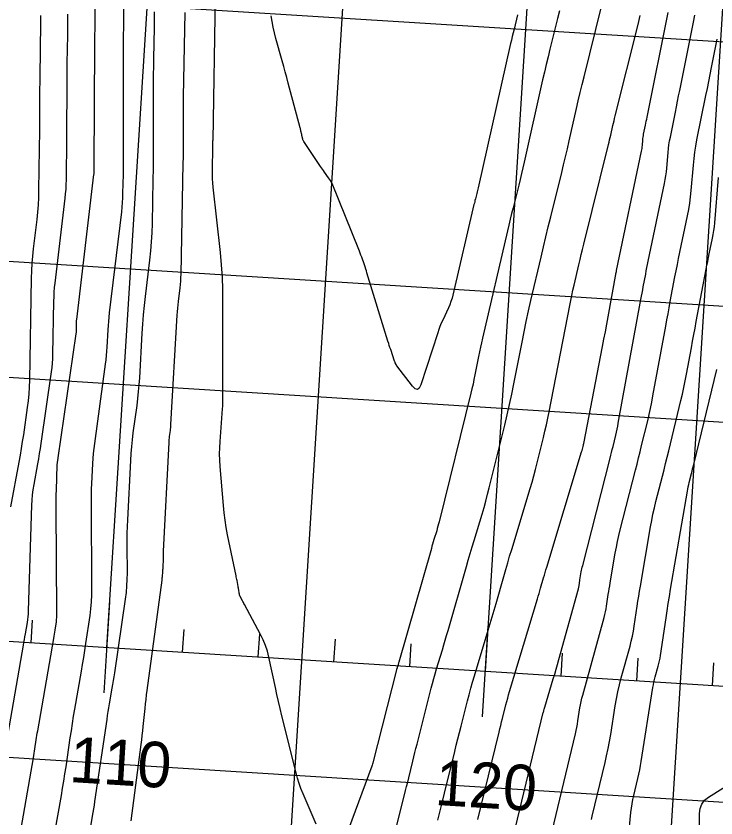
# Model space of a CAD drawing. Extents: x 658976 to 668721, y 639543 to 647196.
# Drawn here: x 661687.6 to 661779.9, y 641890.7 to 641996.4 of the extents above; entities that cross this region are included whole.
import ezdxf

# ---------------------------------------------------------------- set-up
doc = ezdxf.new("R2010")
doc.units = 0
for name, color, linetype in [('Ex_Major Contours', 7, 'Continuous'), ('Ex_Minor Contours', 7, 'Continuous'), ('R_Axis', 7, 'Continuous'), ('R_Axis Annot', 7, 'Continuous'), ('R_Grid', 7, 'Continuous')]:
    doc.layers.add(name, color=color, linetype=linetype)

msp = doc.modelspace()

# ---------------------------------------------------------------- linework, layer by layer
at = {"layer": 'Ex_Major Contours'}
for points in [[(661687.83, 641886.53), (661689.93, 641898.61), (661689.98, 641898.9), (661690.03, 641899.2), (661690.08, 641899.49), (661690.12, 641899.79), (661690.29, 641900.97), (661690.34, 641901.26), (661690.38, 641901.55), (661690.43, 641901.85), (661690.48, 641902.14), (661692.61, 641914.34), (661692.65, 641914.62), (661692.7, 641914.89), (661692.74, 641915.17), (661692.78, 641915.44), (661692.95, 641916.54), (661692.98, 641916.82), (661693.01, 641917.1), (661693.02, 641917.37), (661693.02, 641917.65), (661692.93, 641931.59), (661692.93, 641932.17), (661692.93, 641932.74), (661692.94, 641933.32), (661692.95, 641933.9), (661693.06, 641937.19), (661693.06, 641937.27), (661693.07, 641937.35), (661693.08, 641937.43), (661693.09, 641937.51), (661693.15, 641937.83), (661693.16, 641937.91), (661693.18, 641937.99), (661693.19, 641938.07), (661693.2, 641938.15), (661695.55, 641954.48), (661695.57, 641954.57), (661695.58, 641954.66), (661695.58, 641954.75), (661695.58, 641954.85), (661695.6, 641955.98), (661695.61, 641956.08), (661695.61, 641956.18), (661695.62, 641956.27), (661695.63, 641956.37), (661697.9, 641975.47), (661697.91, 641975.56), (661697.92, 641975.66), (661697.92, 641975.75), (661697.92, 641975.84), (661697.93, 641976.21), (661697.93, 641976.31), (661697.93, 641976.4), (661697.93, 641976.49), (661697.93, 641976.58), (661698.02, 641992.66), (661698.02, 641992.92), (661698.02, 641993.19), (661698.02, 641993.45), (661698.03, 641993.72), (661698.04, 641994.78), (661698.04, 641995.05), (661698.05, 641995.32), (661698.05, 641995.58), (661698.05, 641995.85), (661697.98, 642004.95)], [(661753.76, 641996.52), (661753.29, 641994.63), (661753.17, 641994.16), (661753.05, 641993.69), (661752.94, 641993.21), (661752.83, 641992.74), (661748.54, 641973.74), (661748.5, 641973.55), (661748.46, 641973.37), (661748.42, 641973.19), (661748.37, 641973), (661748.19, 641972.27), (661748.14, 641972.08), (661748.1, 641971.9), (661748.06, 641971.72), (661748.01, 641971.53), (661745.22, 641959.6), (661745.11, 641959.17), (661744.97, 641958.74), (661744.82, 641958.33), (661744.64, 641957.92), (661743.88, 641956.29), (661743.69, 641955.88), (661743.52, 641955.46), (661743.37, 641955.05), (661743.22, 641954.62), (661740.99, 641947.76), (661740.78, 641947.33), (661740.54, 641947.15), (661740.25, 641947.24), (661739.91, 641947.57), (661737.84, 641950.27), (661737.81, 641950.31), (661737.78, 641950.36), (661737.75, 641950.41), (661737.73, 641950.46), (661737.63, 641950.67), (661737.61, 641950.72), (661737.59, 641950.78), (661737.57, 641950.83), (661737.55, 641950.88), (661737.03, 641952.41), (661736.93, 641952.68), (661736.84, 641952.96), (661736.76, 641953.23), (661736.67, 641953.51), (661733.9, 641962.51), (661733.82, 641962.77), (661733.73, 641963.03), (661733.65, 641963.3), (661733.56, 641963.56), (661733.2, 641964.6), (661733.11, 641964.86), (661733.02, 641965.11), (661732.92, 641965.37), (661732.82, 641965.62), (661729.29, 641974.28), (661729.2, 641974.49), (661729.09, 641974.69), (661728.97, 641974.89), (661728.84, 641975.07), (661728.29, 641975.81), (661728.16, 641976), (661728.03, 641976.19), (661727.89, 641976.37), (661727.77, 641976.56), (661725.56, 641979.85), (661725.52, 641979.92), (661725.49, 641979.99), (661725.46, 641980.06), (661725.44, 641980.14), (661725.37, 641980.44), (661725.35, 641980.52), (661725.33, 641980.6), (661725.32, 641980.67), (661725.3, 641980.75), (661725.19, 641981.22), (661725.17, 641981.33), (661725.15, 641981.43), (661725.12, 641981.53), (661725.09, 641981.64), (661723.53, 641987.53), (661723.33, 641988.26), (661723.13, 641989), (661722.93, 641989.74), (661722.72, 641990.47), (661721.9, 641993.41), (661721.7, 641994.15), (661721.53, 641994.89), (661721.39, 641995.64), (661721.26, 641996.39)], [(661752.9, 641887.04), (661757.15, 641904.55), (661757.17, 641904.62), (661757.18, 641904.68), (661757.2, 641904.74), (661757.21, 641904.8), (661757.28, 641905.05), (661757.29, 641905.11), (661757.31, 641905.17), (661757.33, 641905.23), (661757.35, 641905.29), (661758.46, 641909), (661758.65, 641909.64), (661758.84, 641910.28), (661759.02, 641910.92), (661759.2, 641911.56), (661761.78, 641920.87), (661761.8, 641920.97), (661761.82, 641921.07), (661761.84, 641921.17), (661761.86, 641921.27), (661761.92, 641921.68), (661761.94, 641921.78), (661761.95, 641921.88), (661761.97, 641921.98), (661761.98, 641922.08), (661762.16, 641923.12), (661762.2, 641923.32), (661762.24, 641923.53), (661762.29, 641923.73), (661762.34, 641923.93), (661765.96, 641938.1), (661766.05, 641938.48), (661766.15, 641938.86), (661766.24, 641939.24), (661766.34, 641939.62), (661766.71, 641941.15), (661766.8, 641941.53), (661766.88, 641941.92), (661766.96, 641942.3), (661767.04, 641942.69), (661770.02, 641959.02), (661770.1, 641959.44), (661770.18, 641959.86), (661770.25, 641960.28), (661770.33, 641960.7), (661770.65, 641962.37), (661770.73, 641962.79), (661770.81, 641963.21), (661770.9, 641963.63), (661770.98, 641964.05), (661773.13, 641974.31), (661773.23, 641974.81), (661773.31, 641975.32), (661773.38, 641975.83), (661773.43, 641976.34), (661773.6, 641978.4), (661773.66, 641978.91), (661773.72, 641979.42), (661773.8, 641979.93), (661773.9, 641980.43), (661774.56, 641983.71), (661774.7, 641984.42), (661774.85, 641985.14), (661774.99, 641985.85), (661775.13, 641986.57), (661776.76, 641994.67), (661776.94, 641995.58), (661777.11, 641996.49)]]:
    msp.add_lwpolyline(points, dxfattribs=at)
at = {"layer": 'Ex_Minor Contours'}
for points in [[(661692.76, 641888.74), (661693.61, 641893.64), (661693.77, 641894.59), (661693.93, 641895.53), (661694.08, 641896.48), (661694.22, 641897.43), (661694.78, 641901.22), (661694.92, 641902.17), (661695.07, 641903.12), (661695.22, 641904.07), (661695.38, 641905.01), (661696.25, 641910.01), (661696.41, 641910.92), (661696.56, 641911.84), (661696.7, 641912.75), (661696.84, 641913.67), (661697.38, 641917.34), (661697.5, 641918.25), (661697.58, 641919.17), (661697.63, 641920.1), (661697.64, 641921.02), (661697.56, 641932.09), (661697.56, 641932.75), (661697.57, 641933.41), (661697.59, 641934.07), (661697.62, 641934.73), (661697.75, 641937.38), (661697.79, 641938.04), (661697.84, 641938.7), (661697.91, 641939.35), (661698, 641940.01), (661699.42, 641950.49), (661699.49, 641951.05), (661699.55, 641951.62), (661699.6, 641952.18), (661699.64, 641952.74), (661699.77, 641955.01), (661699.81, 641955.57), (661699.86, 641956.13), (661699.91, 641956.7), (661699.97, 641957.26), (661701.56, 641970.56), (661701.63, 641971.17), (661701.68, 641971.79), (661701.71, 641972.41), (661701.73, 641973.02), (661701.78, 641975.5), (661701.79, 641976.12), (661701.8, 641976.73), (661701.8, 641977.35), (661701.8, 641977.97), (661701.79, 641992.45), (661701.79, 641992.77), (661701.79, 641993.08), (661701.79, 641993.39), (661701.8, 641993.71), (661701.82, 641994.96), (661701.82, 641995.27), (661701.83, 641995.58), (661701.82, 641995.89), (661701.82, 641996.21), (661701.62, 642008.21)], [(661727.2, 641889.86), (661725.47, 641893.87), (661725.2, 641894.54), (661724.95, 641895.22), (661724.73, 641895.92), (661724.55, 641896.62), (661722.68, 641904.15), (661722.45, 641905.08), (661722.23, 641906), (661722.02, 641906.93), (661721.82, 641907.86), (661720.96, 641911.88), (661720.77, 641912.65), (661720.52, 641913.4), (661720.22, 641914.13), (661719.87, 641914.84), (661717.74, 641918.81), (661717.68, 641918.93), (661717.61, 641919.06), (661717.54, 641919.19), (661717.48, 641919.31), (661717.19, 641919.87), (661717.15, 641919.97), (661717.11, 641920.08), (661717.08, 641920.18), (661717.06, 641920.3), (661716.99, 641920.74), (661716.97, 641920.85), (661716.95, 641920.96), (661716.93, 641921.08), (661716.91, 641921.19), (661716.77, 641921.95), (661716.74, 641922.11), (661716.71, 641922.27), (661716.67, 641922.44), (661716.64, 641922.6), (661715.51, 641927.99), (661715.33, 641928.95), (661715.18, 641929.91), (661715.05, 641930.87), (661714.96, 641931.84), (661714.54, 641936.99), (661714.49, 641937.82), (661714.47, 641938.65), (661714.48, 641939.47), (661714.53, 641940.3), (661714.86, 641944.6), (661714.88, 641944.93), (661714.9, 641945.26), (661714.91, 641945.59), (661714.91, 641945.93), (661714.9, 641947.25), (661714.9, 641947.58), (661714.9, 641947.91), (661714.9, 641948.25), (661714.9, 641948.58), (661714.91, 641958.7), (661714.89, 641960.33), (661714.83, 641961.95), (661714.72, 641963.58), (661714.57, 641965.2), (661713.63, 641973.82), (661713.58, 641974.37), (661713.54, 641974.91), (661713.53, 641975.46), (661713.53, 641976.01), (661713.59, 641979.16), (661713.59, 641979.23), (661713.59, 641979.3), (661713.59, 641979.38), (661713.59, 641979.45), (661713.59, 641979.74), (661713.59, 641979.81), (661713.59, 641979.88), (661713.59, 641979.95), (661713.6, 641980.03), (661713.92, 641999.04)], [(661736.72, 641885.34), (661738.85, 641893.72), (661738.99, 641894.27), (661739.13, 641894.83), (661739.27, 641895.39), (661739.41, 641895.94), (661739.95, 641898.17), (661740.08, 641898.73), (661740.22, 641899.29), (661740.36, 641899.84), (661740.5, 641900.4), (661742.38, 641907.78), (661742.55, 641908.41), (661742.72, 641909.05), (661742.9, 641909.68), (661743.08, 641910.32), (661743.84, 641912.84), (661744.03, 641913.47), (661744.22, 641914.1), (661744.4, 641914.73), (661744.59, 641915.36), (661747, 641923.8), (661747.25, 641924.67), (661747.51, 641925.53), (661747.76, 641926.4), (661748.02, 641927.26), (661749.07, 641930.72), (661749.33, 641931.58), (661749.57, 641932.45), (661749.8, 641933.33), (661750.03, 641934.2), (661752.07, 641942.46), (661752.4, 641943.82), (661752.71, 641945.18), (661753, 641946.55), (661753.27, 641947.91), (661754.34, 641953.4), (661754.61, 641954.77), (661754.9, 641956.13), (661755.19, 641957.5), (661755.51, 641958.86), (661756.85, 641964.61), (661757.16, 641965.94), (661757.48, 641967.26), (661757.8, 641968.59), (661758.13, 641969.91), (661759.57, 641975.73), (661759.82, 641976.78), (661760.07, 641977.83), (661760.32, 641978.89), (661760.56, 641979.94), (661761.51, 641984.17), (661761.76, 641985.22), (661762, 641986.28), (661762.26, 641987.33), (661762.52, 641988.38), (661764.84, 641997.63)], [(661684.29, 641888.9), (661688.6, 641913.43), (661688.67, 641913.8), (661688.73, 641914.18), (661688.8, 641914.56), (661688.86, 641914.93), (661689.12, 641916.44), (661689.18, 641916.82), (661689.23, 641917.2), (661689.26, 641917.58), (661689.28, 641917.96), (661689.71, 641931.88), (661689.74, 641932.57), (661689.8, 641933.25), (661689.89, 641933.93), (661690, 641934.61), (661690.5, 641937.33), (661690.62, 641938.01), (661690.74, 641938.69), (661690.85, 641939.37), (661690.95, 641940.05), (661692.31, 641949.49), (661692.38, 641950.05), (661692.44, 641950.61), (661692.47, 641951.18), (661692.49, 641951.75), (661692.62, 641958.77), (661692.64, 641959.38), (661692.67, 641959.98), (661692.72, 641960.58), (661692.78, 641961.18), (661694.11, 641972.36), (661694.17, 641972.96), (661694.22, 641973.57), (661694.25, 641974.18), (661694.27, 641974.78), (661694.3, 641977.21), (661694.31, 641977.82), (661694.32, 641978.43), (661694.32, 641979.04), (661694.32, 641979.65), (661694.37, 641988.5), (661694.38, 641989.24), (661694.38, 641989.98), (661694.39, 641990.72), (661694.4, 641991.45), (661694.44, 641994.41), (661694.45, 641995.14), (661694.45, 641995.88), (661694.45, 641996.62)], [(661690.87, 641996.45), (661690.86, 641995.96), (661690.86, 641995.48), (661690.76, 641988.34), (661690.75, 641987.56), (661690.74, 641986.77), (661690.74, 641985.98), (661690.73, 641985.19), (661690.71, 641982.04), (661690.71, 641981.25), (661690.7, 641980.46), (661690.69, 641979.68), (661690.68, 641978.89), (661690.61, 641973.42), (661690.58, 641972.45), (661690.53, 641971.48), (661690.46, 641970.52), (661690.36, 641969.55), (661689.9, 641965.71), (661689.8, 641964.74), (661689.72, 641963.78), (661689.66, 641962.81), (661689.64, 641961.84), (661689.39, 641948.37), (661689.36, 641947.47), (661689.31, 641946.57), (661689.22, 641945.66), (661689.1, 641944.77), (661688.59, 641941.17), (661688.45, 641940.28), (661688.31, 641939.38), (661688.16, 641938.49), (661688, 641937.59), (661686.9, 641931.68)], [(661705.85, 641996.92), (661705.84, 641995.89), (661705.83, 641994.86), (661705.76, 641990.74), (661705.74, 641989.71), (661705.73, 641988.68), (661705.73, 641987.65), (661705.73, 641986.62), (661705.73, 641980.34), (661705.73, 641978.96), (661705.72, 641977.59), (661705.7, 641976.22), (661705.68, 641974.85), (661705.57, 641969.03), (661705.53, 641967.82), (661705.46, 641966.62), (661705.36, 641965.41), (661705.23, 641964.21), (661704.66, 641959.4), (661704.52, 641958.2), (661704.41, 641956.99), (661704.31, 641955.78), (661704.23, 641954.58), (661703.89, 641948.69), (661703.83, 641947.78), (661703.75, 641946.87), (661703.65, 641945.96), (661703.54, 641945.05), (661703.04, 641941.43), (661702.93, 641940.53), (661702.84, 641939.62), (661702.76, 641938.71), (661702.71, 641937.79), (661702.32, 641929.97), (661702.28, 641929.1), (661702.25, 641928.22), (661702.24, 641927.35), (661702.24, 641926.48), (661702.27, 641922.99), (661702.25, 641922.12), (661702.21, 641921.25), (661702.13, 641920.38), (661702.02, 641919.52), (661700.59, 641909.8), (661700.52, 641909.29), (661700.43, 641908.78), (661700.35, 641908.27), (661700.26, 641907.76), (661699.91, 641905.71), (661699.82, 641905.2), (661699.74, 641904.69), (661699.66, 641904.18), (661699.58, 641903.67), (661697.99, 641892.82), (661697.92, 641892.34), (661697.84, 641891.87), (661697.76, 641891.39), (661697.68, 641890.92), (661697.35, 641889.02)], [(661709.87, 641996.82), (661709.68, 641985.74), (661709.67, 641985.01), (661709.66, 641984.28), (661709.66, 641983.55), (661709.66, 641982.82), (661709.66, 641979.91), (661709.66, 641979.18), (661709.66, 641978.45), (661709.65, 641977.72), (661709.64, 641976.99), (661709.35, 641962.34), (661709.33, 641961.89), (661709.31, 641961.44), (661709.27, 641960.99), (661709.22, 641960.54), (661709.01, 641958.75), (661708.96, 641958.3), (661708.92, 641957.85), (661708.88, 641957.4), (661708.85, 641956.95), (661708.01, 641942.52), (661708, 641942.32), (661707.98, 641942.12), (661707.96, 641941.92), (661707.94, 641941.73), (661707.83, 641940.94), (661707.81, 641940.74), (661707.79, 641940.54), (661707.77, 641940.34), (661707.76, 641940.15), (661707.04, 641925.85), (661707.03, 641925.6), (661707.02, 641925.35), (661707.01, 641925.1), (661707.01, 641924.85), (661706.97, 641923.63), (661706.97, 641923.49), (661706.96, 641923.36), (661706.95, 641923.22), (661706.94, 641923.09), (661706.89, 641922.54), (661706.88, 641922.41), (661706.86, 641922.27), (661706.85, 641922.14), (661706.83, 641922), (661704.88, 641907.48), (661704.8, 641906.89), (661704.73, 641906.3), (661704.66, 641905.7), (661704.6, 641905.11), (661704.35, 641902.73), (661704.29, 641902.14), (661704.22, 641901.54), (661704.15, 641900.95), (661704.08, 641900.36), (661702.77, 641890.3)], [(661759.29, 641997.07), (661759.04, 641996.05), (661758.03, 641992.01), (661757.78, 641990.99), (661757.53, 641989.98), (661757.29, 641988.97), (661757.06, 641987.95), (661754.61, 641977.11), (661754.44, 641976.36), (661754.27, 641975.6), (661754.09, 641974.85), (661753.9, 641974.1), (661753.16, 641971.09), (661752.97, 641970.33), (661752.79, 641969.58), (661752.61, 641968.83), (661752.43, 641968.07), (661749.12, 641953.92), (661748.98, 641953.31), (661748.85, 641952.71), (661748.72, 641952.1), (661748.6, 641951.5), (661748.13, 641949.06), (661748.01, 641948.46), (661747.88, 641947.85), (661747.74, 641947.25), (661747.6, 641946.65), (661743.41, 641929.71), (661743.33, 641929.42), (661743.26, 641929.12), (661743.17, 641928.83), (661743.09, 641928.54), (661742.73, 641927.37), (661742.64, 641927.08), (661742.56, 641926.78), (661742.47, 641926.49), (661742.39, 641926.2), (661738.09, 641911.19), (661738.06, 641911.1), (661738.04, 641911.02), (661738.01, 641910.93), (661737.99, 641910.85), (661737.89, 641910.52), (661737.86, 641910.43), (661737.84, 641910.35), (661737.81, 641910.26), (661737.79, 641910.18), (661734.68, 641897.95), (661734.67, 641897.91), (661734.66, 641897.87), (661734.65, 641897.84), (661734.64, 641897.8), (661734.59, 641897.65), (661734.58, 641897.62), (661734.57, 641897.58), (661734.56, 641897.54), (661734.54, 641897.51), (661730.59, 641886.82)], [(661743.25, 641890.38), (661743.47, 641891.26), (661743.7, 641892.15), (661743.92, 641893.03), (661744.13, 641893.92), (661745.47, 641899.41), (661745.67, 641900.25), (661745.88, 641901.08), (661746.09, 641901.92), (661746.3, 641902.75), (661747.15, 641906.09), (661747.36, 641906.92), (661747.59, 641907.76), (661747.83, 641908.58), (661748.07, 641909.41), (661749.88, 641915.41), (661750.14, 641916.3), (661750.4, 641917.18), (661750.66, 641918.07), (661750.92, 641918.96), (661751.93, 641922.51), (661752.19, 641923.4), (661752.45, 641924.28), (661752.71, 641925.17), (661752.98, 641926.05), (661755.42, 641934.12), (661755.67, 641934.95), (661755.9, 641935.78), (661756.13, 641936.62), (661756.34, 641937.46), (661757.17, 641940.82), (661757.37, 641941.66), (661757.57, 641942.5), (661757.75, 641943.35), (661757.92, 641944.2), (661760.64, 641958.21), (661760.77, 641958.89), (661760.91, 641959.56), (661761.06, 641960.24), (661761.22, 641960.91), (661761.85, 641963.6), (661762, 641964.27), (661762.16, 641964.95), (661762.33, 641965.62), (661762.49, 641966.29), (661765.74, 641979.44), (661765.82, 641979.75), (661765.89, 641980.06), (661765.97, 641980.38), (661766.04, 641980.69), (661766.32, 641981.95), (661766.39, 641982.26), (661766.47, 641982.58), (661766.54, 641982.89), (661766.62, 641983.2), (661769.66, 641995.28), (661769.75, 641995.67), (661769.84, 641996.05), (661769.92, 641996.43)], [(661748.51, 641890.48), (661751.31, 641901.98), (661751.42, 641902.43), (661751.53, 641902.88), (661751.64, 641903.33), (661751.76, 641903.78), (661752.21, 641905.57), (661752.33, 641906.02), (661752.45, 641906.46), (661752.58, 641906.91), (661752.71, 641907.35), (661756.38, 641919.57), (661756.49, 641919.92), (661756.59, 641920.26), (661756.69, 641920.61), (661756.79, 641920.95), (661757.19, 641922.34), (661757.29, 641922.69), (661757.39, 641923.03), (661757.49, 641923.38), (661757.6, 641923.72), (661762.2, 641938.93), (661762.23, 641939.01), (661762.25, 641939.1), (661762.28, 641939.19), (661762.3, 641939.28), (661762.39, 641939.64), (661762.41, 641939.73), (661762.43, 641939.82), (661762.45, 641939.91), (661762.47, 641940.01), (661764.95, 641952.81), (661765.14, 641953.79), (661765.33, 641954.76), (661765.51, 641955.74), (661765.69, 641956.72), (661766.76, 641962.55), (661766.76, 641962.58), (661766.77, 641962.6), (661766.77, 641962.63), (661766.78, 641962.65), (661766.79, 641962.75), (661766.8, 641962.78), (661766.8, 641962.8), (661766.81, 641962.83), (661766.81, 641962.85), (661770.1, 641978.56), (661770.14, 641978.74), (661770.17, 641978.93), (661770.19, 641979.12), (661770.21, 641979.3), (661770.28, 641980.05), (661770.29, 641980.24), (661770.32, 641980.43), (661770.35, 641980.61), (661770.38, 641980.8), (661770.63, 641982), (661770.68, 641982.26), (661770.73, 641982.52), (661770.78, 641982.78), (661770.84, 641983.04), (661773.6, 641996.86)], [(661758.04, 641887.84), (661761.38, 641901.77), (661761.47, 641902.19), (661761.56, 641902.61), (661761.64, 641903.04), (661761.71, 641903.46), (661761.98, 641905.18), (661762.06, 641905.6), (661762.14, 641906.03), (661762.24, 641906.45), (661762.35, 641906.87), (661765.18, 641917.1), (661765.27, 641917.47), (661765.36, 641917.85), (661765.43, 641918.22), (661765.5, 641918.6), (661765.72, 641920.13), (661765.78, 641920.51), (661765.84, 641920.89), (661765.9, 641921.28), (661765.97, 641921.66), (661766.64, 641925.57), (661766.78, 641926.35), (661766.94, 641927.12), (661767.11, 641927.89), (661767.3, 641928.66), (661769.3, 641936.5), (661769.51, 641937.31), (661769.71, 641938.13), (661769.91, 641938.94), (661770.11, 641939.76), (661770.91, 641943.03), (661771.1, 641943.84), (661771.28, 641944.66), (661771.45, 641945.49), (661771.61, 641946.31), (661773.29, 641955.49), (661773.44, 641956.31), (661773.59, 641957.12), (661773.74, 641957.93), (661773.89, 641958.75), (661774.51, 641962), (661774.66, 641962.81), (661774.82, 641963.62), (661774.99, 641964.43), (661775.15, 641965.24), (661776.16, 641970.06), (661776.32, 641970.88), (661776.46, 641971.71), (661776.57, 641972.55), (661776.65, 641973.38), (661776.93, 641976.74), (661777.02, 641977.58), (661777.12, 641978.41), (661777.25, 641979.24), (661777.41, 641980.07), (661778.59, 641985.9), (661778.78, 641986.83), (661778.96, 641987.76), (661779.15, 641988.68), (661779.34, 641989.61), (661780.08, 641993.31)], [(661763.5, 641890.45), (661763.6, 641890.9), (661765.29, 641897.96), (661765.5, 641898.88), (661765.7, 641899.81), (661765.87, 641900.74), (661766.03, 641901.68), (661766.62, 641905.43), (661766.78, 641906.37), (661766.97, 641907.29), (661767.18, 641908.21), (661767.42, 641909.13), (661768.58, 641913.32), (661768.75, 641913.97), (661768.9, 641914.62), (661769.02, 641915.28), (661769.13, 641915.94), (661769.53, 641918.59), (661769.63, 641919.25), (661769.73, 641919.91), (661769.84, 641920.57), (661769.95, 641921.23), (661771.29, 641929.03), (661771.44, 641929.88), (661771.61, 641930.72), (661771.8, 641931.56), (661772, 641932.39), (661772.85, 641935.73), (661773.07, 641936.56), (661773.28, 641937.4), (661773.48, 641938.23), (661773.69, 641939.07), (661775.3, 641945.68), (661775.5, 641946.54), (661775.69, 641947.41), (661775.87, 641948.27), (661776.04, 641949.15), (661776.67, 641952.64), (661776.83, 641953.51), (661776.99, 641954.38), (661777.16, 641955.25), (661777.32, 641956.12), (661778.63, 641963.01), (661778.73, 641963.52), (661778.83, 641964.03), (661778.93, 641964.54), (661779.03, 641965.05), (661779.46, 641967.08), (661779.56, 641967.59), (661779.64, 641968.1), (661779.71, 641968.61), (661779.76, 641969.13), (661780.26, 641975.08)], [(661768.4, 641888.15), (661768.71, 641891.39), (661768.77, 641891.96), (661768.86, 641892.53), (661768.96, 641893.09), (661769.09, 641893.65), (661769.62, 641895.88), (661769.75, 641896.44), (661769.87, 641897), (661769.97, 641897.57), (661770.07, 641898.13), (661771.6, 641907.86), (661771.66, 641908.22), (661771.73, 641908.57), (661771.82, 641908.93), (661771.91, 641909.28), (661772.29, 641910.68), (661772.39, 641911.03), (661772.47, 641911.38), (661772.54, 641911.74), (661772.6, 641912.1), (661773.33, 641917.04), (661773.47, 641917.98), (661773.62, 641918.93), (661773.77, 641919.87), (661773.93, 641920.81), (661776.15, 641933.73), (661776.2, 641934.02), (661776.26, 641934.32), (661776.33, 641934.62), (661776.4, 641934.91), (661776.7, 641936.08), (661776.77, 641936.37), (661776.84, 641936.67), (661776.92, 641936.96), (661776.99, 641937.25), (661780.04, 641949.77)], [(661777.75, 641888.44), (661777.75, 641891.26), (661777.82, 641891.92), (661778.04, 641892.5), (661778.41, 641893), (661778.94, 641893.42), (661784.93, 641897.21)]]:
    msp.add_lwpolyline(points, dxfattribs=at)
at = {"layer": 'R_Axis'}
for p, q in [((660402.17, 641994.63), (661899.22, 641900.61)), ((661699.24, 641907.15), (661699.99, 641919.13)), ((661689.63, 641913.77), (661689.82, 641916.76)), ((661749.14, 641904.02), (661749.89, 641916)), ((661709.59, 641912.52), (661709.78, 641915.51)), ((661719.57, 641911.89), (661719.76, 641914.88)), ((661729.55, 641911.26), (661729.74, 641914.26)), ((661739.53, 641910.64), (661739.72, 641913.63)), ((661759.49, 641909.38), (661759.68, 641912.38)), ((661769.47, 641908.75), (661769.66, 641911.75)), ((661779.45, 641908.13), (661779.64, 641911.12))]:
    msp.add_line(p, q, dxfattribs=at)
at = {"layer": 'R_Grid'}
for p, q in [((661699.61, 641913.14), (661712.15, 642112.75)), ((661749.51, 641910.01), (661762.05, 642109.62)), ((661721.23, 641846.42), (661736.9, 642095.93)), ((661771.13, 641843.29), (661786.81, 642092.79)), ((660405.3, 642044.53), (661902.35, 641950.51)), ((661630.83, 642002.39), (663127.88, 641908.37)), ((660402.17, 641994.63), (661899.22, 641900.61)), ((661627.7, 641952.49), (663124.75, 641858.47)), ((661624.56, 641902.59), (663121.61, 641808.57))]:
    msp.add_line(p, q, dxfattribs=at)

# ---------------------------------------------------------------- texts
at = {"layer": 'R_Axis Annot'}
for s, p in [('110', (661694.55, 641895.42)), ('120', (661742.75, 641892.4))]:
    msp.add_text(s, height=6, rotation=356.4063, dxfattribs=at).set_placement(p)

doc.saveas('drawing.dxf')
